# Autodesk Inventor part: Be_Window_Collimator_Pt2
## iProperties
Shininess: 64.0
Length Units: 11269
Angle Units: 11279
Time Units: 11290
Mass Units: 11283
Length Display Precision: 3
Angle Display Precision: 2
Compacted: True
Part Number: Be_Window_Collimator_Pt2
Document SubType Name: Modeling
Created: 2004-07
Material: Lead
Designer: John Blackburn
Manufacturer: Standard
Standards Organization: Custom
Project: mucap
Description: Be Window Collimator Cap
Density: 0.0
Volumn: 0.0
Area: 0.0
PropertySet Name: Model Information
Control State: 0
Master: False
Checked Out: False
Author: John Blackburn
Title: Be Window Collimator Cap
Subject: mucap
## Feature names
1. Extrusion1
2. Hole1
3. Circular Pattern1
4. Extrusion3
